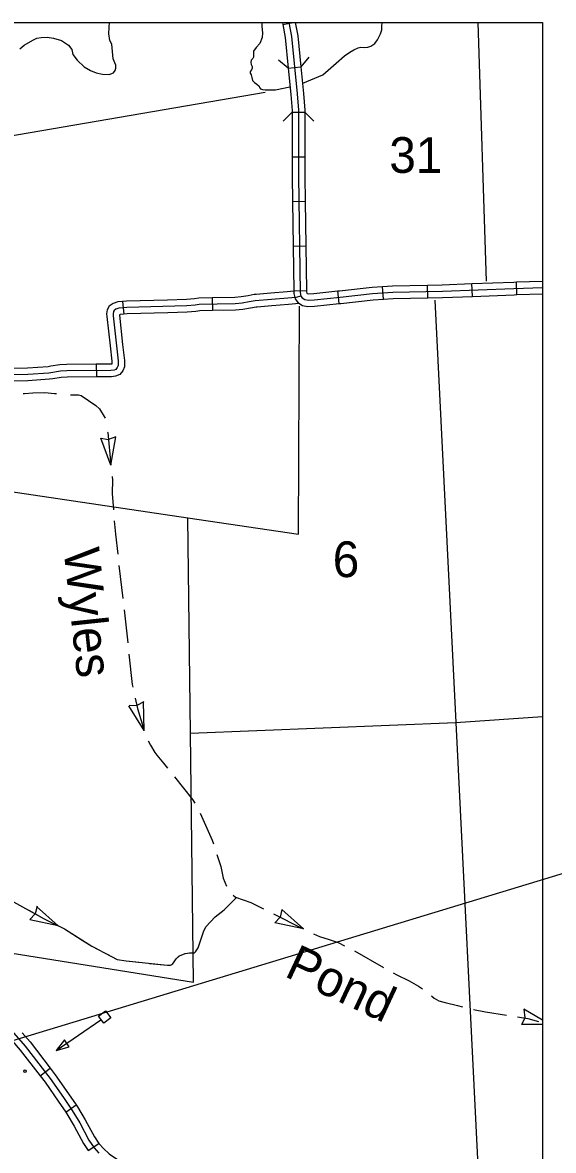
# Model space of a CAD drawing. Extents: x 155 to 3386, y 68 to 2138.
# Drawn here: x 2166.4 to 2345.9, y 927.8 to 1309 of the extents above; entities that cross this region are included whole.
import ezdxf

# ---------------------------------------------------------------- set-up
doc = ezdxf.new("R2010")
doc.units = 0
for name, color, linetype in [('2', 7, 'Continuous'), ('Default', 7, 'Continuous'), ('E_No Plot', 7, 'Continuous'), ('Level 32', 7, 'Continuous'), ('Level 35', 7, 'Continuous'), ('Level 38', 7, 'Continuous'), ('Level 43', 7, 'Continuous'), ('Level 45', 7, 'Continuous'), ('Level 5', 7, 'Continuous'), ('Level 56', 7, 'Continuous')]:
    doc.layers.add(name, color=color, linetype=linetype)

msp = doc.modelspace()

# ---------------------------------------------------------------- linework, layer by layer
at = {"layer": '2'}
msp.add_line((1718.72, 829.66), (2409.24, 1039.86), dxfattribs=at)
at = {"layer": 'Default'}
msp.add_lwpolyline([(1150.5, 1308.99), (2342.15, 1308.99), (2342.15, 348.58), (1150.5, 348.58)], close=True, dxfattribs=at)
at = {"layer": 'E_No Plot'}
msp.add_lwpolyline([(1150.5, 1308.99), (2342.15, 1308.99), (2342.15, 348.58), (1150.5, 348.58)], close=True, dxfattribs=at)
msp.add_lwpolyline([(1150.5, 1308.99), (2342.15, 1308.99), (2342.15, 348.58), (1150.5, 348.58)], close=True, dxfattribs=at)
at = {"layer": 'Level 32'}
for p, q in [((2254.39, 1308.33), (2257.94, 1308.99)), ((2256.25, 1293.55), (2260.52, 1293.98)), ((2257.53, 1278.74), (2261.82, 1278.74)), ((2257.55, 1263.65), (2261.84, 1263.66)), ((2257.68, 1248.54), (2261.96, 1248.6)), ((2257.88, 1233.46), (2262.16, 1233.52)), ((2288.37, 1215.47), (2288.09, 1219.75)), ((2303.36, 1215.97), (2303.25, 1220.25)), ((2318.47, 1216.47), (2318.3, 1220.76)), ((2333.54, 1217.05), (2333.38, 1221.33)), ((2258.08, 1218.37), (2262.37, 1218.43)), ((2273.45, 1214.05), (2272.98, 1218.31)), ((2172.36, 953.03), (2175.76, 955.64)), ((2181.02, 940.81), (2184.55, 943.24)), ((2188.63, 927.83), (2192.18, 930.22))]:
    msp.add_line(p, q, dxfattribs=at)
for points in [[(2254.26, 1308.99), (2254.39, 1308.33)], [(2254.39, 1308.33), (2255.21, 1303.92), (2256.25, 1293.55)], [(2256.44, 1308.99), (2257.33, 1304.23), (2259.29, 1284.87), (2259.67, 1279.36), (2259.71, 1256.96), (2260.23, 1217.73), (2260.53, 1216.57), (2260.99, 1215.96), (2261.8, 1215.44), (2263.03, 1215.22), (2265, 1215.26), (2273.74, 1216.23), (2284.76, 1217.38), (2291.6, 1217.83), (2308.31, 1218.23), (2332.52, 1219.15), (2342.15, 1219.51)], [(2258.62, 1308.99), (2259.45, 1304.53), (2260.52, 1293.98)], [(2256.25, 1293.55), (2257.15, 1284.68), (2257.53, 1279.28), (2257.53, 1278.74)], [(2260.52, 1293.98), (2261.42, 1285.05), (2261.81, 1279.44), (2261.82, 1278.74)], [(2257.53, 1278.74), (2257.55, 1263.65)], [(2261.82, 1278.74), (2261.84, 1263.66)], [(2257.55, 1263.65), (2257.56, 1256.95), (2257.68, 1248.54)], [(2261.84, 1263.66), (2261.85, 1256.98), (2261.96, 1248.6)], [(2257.68, 1248.54), (2257.88, 1233.46)], [(2261.96, 1248.6), (2262.16, 1233.52)], [(2257.88, 1233.46), (2258.08, 1218.37)], [(2262.16, 1233.52), (2262.37, 1218.43)], [(2272.98, 1218.31), (2273.51, 1218.37), (2284.58, 1219.52), (2288.09, 1219.75)], [(2288.09, 1219.75), (2291.51, 1219.97), (2303.25, 1220.25)], [(2303.25, 1220.25), (2308.24, 1220.37), (2318.3, 1220.76)], [(2318.3, 1220.76), (2332.44, 1221.29), (2333.38, 1221.33)], [(2333.38, 1221.33), (2342.15, 1221.65)], [(2258.08, 1218.37), (2258.09, 1217.44), (2258.56, 1215.62), (2259.51, 1214.36), (2261, 1213.41), (2262.86, 1213.08), (2265.14, 1213.12), (2273.45, 1214.05)], [(2262.37, 1218.43), (2262.37, 1218.01), (2262.49, 1217.54), (2262.59, 1217.48), (2263.2, 1217.37), (2264.86, 1217.4), (2272.98, 1218.31)], [(2288.37, 1215.47), (2291.7, 1215.69), (2303.36, 1215.97)], [(2303.36, 1215.97), (2308.37, 1216.09), (2318.47, 1216.47)], [(2318.47, 1216.47), (2332.6, 1217.01), (2333.54, 1217.05)], [(2333.54, 1217.05), (2342.15, 1217.36)], [(2273.45, 1214.05), (2273.97, 1214.1), (2284.94, 1215.25), (2288.37, 1215.47)], [(2161.13, 970.12), (2167.32, 963.12), (2175.75, 952.13), (2180.24, 945.72), (2183.24, 941.36), (2185.75, 937.1), (2188.87, 931.3), (2190.62, 928.7), (2192.23, 926.95)], [(2163.06, 964.71), (2165.67, 961.76), (2172.36, 953.03)], [(2166.27, 967.55), (2168.98, 964.49), (2175.76, 955.64)], [(2172.36, 953.03), (2174.02, 950.87), (2178.48, 944.49), (2181.02, 940.81)], [(2175.76, 955.64), (2177.48, 953.4), (2182, 946.94), (2184.55, 943.24)], [(2184.55, 943.24), (2185.05, 942.52), (2187.62, 938.15), (2190.71, 932.41), (2192.18, 930.22)], [(2181.02, 940.81), (2181.44, 940.21), (2183.89, 936.05), (2187.03, 930.2), (2188.63, 927.83)], [(2192.18, 930.22), (2192.31, 930.03), (2193.75, 928.47), (2195.72, 926.67), (2198.22, 924.98), (2203.39, 922.29), (2203.41, 922.28)]]:
    msp.add_lwpolyline(points, dxfattribs=at)
at = {"layer": 'Level 35'}
for points in [[(2165.5, 1300.08), (2166.99, 1301.32), (2169.95, 1303.07), (2171.25, 1303.67), (2172.77, 1303.99), (2174.8, 1304.05), (2176.93, 1303.73), (2179.57, 1302.88), (2181.95, 1301.39), (2183.06, 1299.86), (2183.44, 1298.18), (2184.87, 1296.24), (2187.25, 1294.05), (2189.44, 1292.78), (2191.32, 1292.05), (2193.48, 1291.6), (2195.67, 1291.44), (2197.16, 1291.95), (2197.73, 1292.78), (2198.01, 1293.6), (2197.98, 1294.56), (2197.09, 1296.78), (2196.62, 1301.73), (2195.92, 1302.88), (2195.57, 1305.17), (2195.7, 1307.48), (2195.82, 1308.99)], [(2247.32, 1308.99), (2247.34, 1307.66), (2247.53, 1305.5), (2247.4, 1303.97), (2246.58, 1301.91), (2245.4, 1300.51), (2244.54, 1299.31), (2244.51, 1298.19), (2244.54, 1297.29), (2244.26, 1296.85), (2243.72, 1296.28), (2243.56, 1295.51), (2243.65, 1294.85), (2244, 1294.18), (2244.07, 1293.58), (2243.85, 1293), (2243.46, 1292.57), (2243.35, 1292.23), (2243.39, 1291.85), (2243.68, 1291.38), (2243.88, 1290.39), (2244.14, 1289.45), (2244.84, 1288.74), (2245.63, 1288.14), (2246.35, 1287.52), (2246.54, 1287.06), (2246.87, 1286.61), (2247.52, 1286.36), (2248.47, 1286.31), (2251.9, 1286.22), (2256.74, 1287.25)], [(2261.21, 1288.49), (2267.95, 1291.31), (2272.46, 1295.31), (2275.25, 1297.71), (2277.06, 1298.97), (2278.44, 1299.79), (2279.87, 1300.46), (2280.79, 1300.62), (2282.12, 1300.6), (2283.09, 1300.68), (2284.19, 1301.05), (2285.5, 1301.94), (2286.41, 1303.14), (2287.46, 1305.18), (2287.82, 1306.57), (2287.84, 1307.69), (2287.95, 1308.99)]]:
    msp.add_lwpolyline(points, dxfattribs=at)
at = {"layer": 'Level 38'}
for points in [[(2256.25, 1293.55), (2252.94, 1296.26)], [(2263.23, 1297.3), (2260.52, 1293.98)], [(2254.5, 1275.7), (2257.53, 1278.74)], [(2261.82, 1278.74), (2264.85, 1275.72)]]:
    msp.add_lwpolyline(points, dxfattribs=at)
at = {"layer": 'Level 43'}
for p, q in [((2196.32, 1159.36), (2192.85, 1168.53)), ((2192.85, 1168.53), (2195.43, 1168.11)), ((2197.9, 1169.04), (2195.46, 1168.12)), ((2196.32, 1159.36), (2197.9, 1169.04)), ((2207.42, 1079.43), (2205.11, 1078.22)), ((2207.55, 1069.77), (2207.26, 1079.57)), ((2207.55, 1069.77), (2202.39, 1078.11)), ((2202.47, 1078.32), (2205.07, 1078.21)), ((2171.33, 1010.34), (2170.71, 1007.81)), ((2178.52, 1003.75), (2171.18, 1010.25)), ((2168.9, 1005.89), (2170.7, 1007.78)), ((2251.75, 1004.7), (2253.49, 1006.64)), ((2254.05, 1009.23), (2253.51, 1006.67)), ((2261.34, 1002.67), (2254.05, 1009.23)), ((2178.52, 1003.75), (2168.91, 1005.71)), ((2261.34, 1002.67), (2251.75, 1004.7)), ((2335.23, 970.44), (2336.18, 972.57)), ((2335.87, 975.55), (2336.18, 972.6)), ((2342.15, 971.83), (2335.87, 975.55)), ((2342.15, 970.37), (2335.23, 970.44))]:
    msp.add_line(p, q, dxfattribs=at)
for points in [[(2166.58, 1183.62), (2167.07, 1183.62), (2169.91, 1183.88), (2173.91, 1183.94), (2177.27, 1183.62), (2177.87, 1183.68)], [(2182.63, 1183.14), (2182.86, 1183.16), (2185.31, 1183.16), (2186.22, 1182.97), (2188.67, 1181.29), (2191.25, 1179.61), (2192.46, 1178.47), (2194.37, 1175.27)], [(2195.18, 1170.62), (2195.2, 1170.5), (2196.32, 1159.36)], [(2196.69, 1155.61), (2196.82, 1154.35), (2196.69, 1149.96)], [(2196.69, 1149.96), (2196.69, 1149.89), (2197.13, 1144.32)], [(2197.43, 1140.56), (2197.79, 1136.07), (2198.58, 1129.31)], [(2199.02, 1125.56), (2200.34, 1114.33)], [(2200.75, 1110.58), (2201.98, 1099.33)], [(2202.39, 1095.58), (2203.51, 1085.28), (2203.71, 1084.35)], [(2204.54, 1080.67), (2205.31, 1077.22), (2207.55, 1069.77)], [(2208.89, 1066.26), (2209.7, 1064.81), (2211.12, 1062.36), (2211.85, 1061.46)], [(2211.85, 1061.46), (2214.03, 1058.74), (2215.39, 1057.05)], [(2217.76, 1054.11), (2223.91, 1046.47), (2224.64, 1045.15)], [(2226.47, 1041.85), (2230.56, 1032.65), (2230.95, 1031.47)], [(2232.14, 1027.89), (2233.5, 1023.84), (2234.21, 1019.83), (2235.41, 1017.12)], [(2237.66, 1014.12), (2238.4, 1013.38), (2243.57, 1011.57), (2247.89, 1009.49)], [(2161.34, 1012.92), (2173.71, 1006.15), (2180.62, 1002.7), (2189.9, 996.87), (2198.46, 992.4), (2201.49, 991.9), (2215.45, 990.39), (2216.46, 990.46), (2217.11, 990.82), (2217.68, 991.54), (2218.33, 992.62), (2219.48, 993.63), (2221.42, 994.35), (2222.93, 994.63), (2223.94, 994.63), (2224.52, 994.63), (2224.88, 994.92), (2225.81, 996.29), (2227.68, 1002.05), (2228.4, 1003.42), (2231.57, 1006.8), (2234.59, 1009.1), (2237.18, 1011.69), (2238.69, 1013.28)], [(2230.9, 1006.09), (2231.57, 1006.8), (2234.59, 1009.1), (2237.18, 1011.69), (2238.69, 1013.28)], [(2168.5, 1009), (2173.71, 1006.15), (2178.52, 1003.75)], [(2251.26, 1007.8), (2260.87, 1002.91), (2261.35, 1002.69)], [(2222.81, 994.61), (2222.93, 994.63), (2223.94, 994.63), (2224.52, 994.63), (2224.88, 994.92), (2225.81, 996.29), (2227.68, 1002.05), (2228.35, 1003.32)], [(2181.82, 1001.94), (2186.61, 998.93)], [(2186.61, 998.93), (2189.9, 996.87), (2191.47, 996.04)], [(2264.76, 1001.08), (2266.81, 1000.12), (2270.05, 999.1)], [(2270.05, 999.1), (2273.14, 998.12), (2275.29, 997.02)], [(2278.64, 995.28), (2288.46, 989.67)], [(2194.82, 994.3), (2198.46, 992.4), (2201.49, 991.9), (2205.6, 991.45)], [(2209.35, 991.05), (2215.45, 990.39), (2216.46, 990.46), (2217.11, 990.82), (2217.68, 991.54), (2218.33, 992.62), (2219.27, 993.44)], [(2291.74, 987.8), (2292.89, 987.14), (2297.15, 985.2), (2300.25, 983.39), (2301.64, 982.39)], [(2304.63, 980.09), (2305.54, 979.33), (2307.09, 978.42), (2309.22, 977.78), (2313.42, 976.81), (2315.15, 976.33)], [(2318.81, 975.43), (2322.91, 974.68), (2329.97, 973.56)], [(2333.69, 972.97), (2337.24, 972.41), (2340.77, 971.43)]]:
    msp.add_lwpolyline(points, dxfattribs=at)
at = {"layer": 'Level 45'}
for p, q in [((2230.49, 1215.93), (2230.6, 1211.64)), ((2200.21, 1214.72), (2200.61, 1210.45)), ((2191.36, 1193.5), (2191.4, 1189.21))]:
    msp.add_line(p, q, dxfattribs=at)
for points in [[(2260.53, 1216.57), (2258.74, 1216.12), (2256.09, 1215.86), (2250.54, 1215.41), (2245.05, 1214.96), (2243.05, 1214.57), (2240.6, 1214.12), (2238.27, 1213.99), (2226.14, 1213.67), (2224.78, 1213.47), (2221.94, 1213.22), (2201.67, 1212.7), (2199.02, 1212.45), (2197.98, 1212.13), (2197.34, 1211.68), (2197.14, 1211.29), (2197.01, 1210.52), (2197.08, 1209.87), (2198.69, 1194.69), (2198.69, 1193.08), (2198.43, 1192.37), (2197.98, 1191.79), (2197.34, 1191.53), (2196.3, 1191.4), (2181.39, 1191.27), (2179.26, 1191.14), (2175.26, 1190.56), (2168.16, 1190.11), (2161.51, 1189.98)], [(2230.49, 1215.93), (2225.96, 1215.81), (2224.53, 1215.6), (2221.82, 1215.36), (2215.43, 1215.19)], [(2245.37, 1217.14), (2244.76, 1217.09), (2242.65, 1216.68), (2240.34, 1216.25), (2238.18, 1216.13), (2230.49, 1215.93)], [(2258.08, 1218.21), (2255.9, 1218), (2250.36, 1217.55), (2245.37, 1217.14)], [(2200.21, 1214.72), (2198.59, 1214.57), (2197.03, 1214.08), (2195.66, 1213.12), (2195.08, 1211.96), (2194.85, 1210.59), (2194.95, 1209.65), (2196, 1199.75)], [(2215.43, 1215.19), (2201.54, 1214.84), (2200.21, 1214.72)], [(2245.72, 1212.86), (2245.34, 1212.83), (2243.45, 1212.47), (2240.85, 1211.99), (2238.36, 1211.85), (2230.6, 1211.64)], [(2259.94, 1214.09), (2256.28, 1213.73), (2250.71, 1213.28), (2245.72, 1212.86)], [(2200.61, 1210.45), (2199.44, 1210.34), (2199.19, 1210.26), (2199.21, 1210.09), (2200.26, 1200.21)], [(2215.54, 1210.91), (2201.8, 1210.56), (2200.61, 1210.45)], [(2230.6, 1211.64), (2226.32, 1211.53), (2225.03, 1211.35), (2222.06, 1211.08), (2215.54, 1210.91)], [(2196, 1199.75), (2196.55, 1194.58), (2196.55, 1193.59), (2196.16, 1193.54), (2191.36, 1193.5)], [(2200.26, 1200.21), (2200.84, 1194.81), (2200.84, 1192.7), (2200.33, 1191.32), (2199.32, 1190.01), (2197.88, 1189.44), (2196.45, 1189.26), (2191.4, 1189.21)], [(2191.36, 1193.5), (2181.32, 1193.41), (2179.04, 1193.27), (2176.02, 1192.84)], [(2176.02, 1192.84), (2175.04, 1192.69), (2168.07, 1192.25), (2161.34, 1192.12), (2160.98, 1192.07)], [(2176.64, 1188.59), (2175.48, 1188.43), (2168.25, 1187.97), (2161.68, 1187.84), (2161.57, 1187.82)], [(2191.4, 1189.21), (2181.47, 1189.13), (2179.48, 1189.01), (2176.64, 1188.59)]]:
    msp.add_lwpolyline(points, dxfattribs=at)
at = {"layer": 'Level 5'}
for points in [[(2320.31, 1308.99), (2323.1, 1221.64)], [(2248.39, 1285.33), (2130.82, 1265.17)], [(2259.66, 1136.07), (2260.02, 1213.18)], [(2305.75, 1215.2), (2312.91, 1072.42)], [(2095.69, 1160.38), (2222.31, 1141.66)], [(2222.31, 1141.66), (2259.66, 1136.07)], [(2223.24, 1068.88), (2222.31, 1141.66)], [(2223.24, 1068.88), (2312.91, 1072.42)], [(2312.91, 1072.42), (2342.15, 1074.45)], [(2312.91, 1072.42), (2320.42, 920.32)], [(2224.22, 984.75), (2223.24, 1068.88)], [(2162.95, 994.49), (2224.22, 984.75)]]:
    msp.add_lwpolyline(points, dxfattribs=at)
at = {"layer": 'Level 56'}
msp.add_lwpolyline([(2177.77, 961.57), (2192.94, 971.98)], dxfattribs=at)
for points in [[(2192.08, 973.18), (2194.44, 974.99), (2196.25, 972.62), (2193.89, 970.81)], [(2182.2, 962.84), (2180.55, 965.24), (2177.77, 961.57)]]:
    msp.add_lwpolyline(points, close=True, dxfattribs=at)
msp.add_circle((2167.26, 954.63), 0.429, dxfattribs=at)

# ---------------------------------------------------------------- texts
at = {"layer": 'Level 43'}
for s, rotation, p in [('Wyles', 276.1179, (2180.29, 1130.84)), ('Pond', 334.9197, (2254.55, 986.83))]:
    msp.add_text(s, height=12.069, rotation=rotation, dxfattribs=at).set_placement(p)
at = {"layer": 'Level 5'}
for s, height, p in [('31', 12.069, (2290.38, 1258.19)), ('6', 12.07, (2271.26, 1121.58))]:
    msp.add_text(s, height=height, dxfattribs=at).set_placement(p)

doc.saveas('drawing.dxf')
